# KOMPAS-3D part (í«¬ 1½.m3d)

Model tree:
1. Эскиз:1
2. Операция выдавливания:1
     Расстояние 1 = 2
3. Эскиз:2
4. Операция выдавливания:2
     Расстояние 1 = 5
5. Эскиз:3
6. Операция выдавливания:3
     Расстояние 1 = 2
7. Эскиз:4
8. Операция выдавливания:4
     Расстояние 1 = 60
9. Эскиз:5
10. Операция выдавливания:5
     Расстояние 1 = 2
11. Эскиз:6
12. Операция выдавливания:6
     Расстояние 1 = 4.5
13. Эскиз:7
14. Операция выдавливания:7
     Расстояние 1 = 2
15. Скругление:1
     Радиус = 1
16. Скругление:2
     Радиус = 1
17. Эскиз:8
18. Вырезать элемент выдавливания:1
     Расстояние 1 = 10; Угол 1 = 35
19. Эскиз:9
20. Вырезать элемент выдавливания:2
     Расстояние 1 = 10; Угол 1 = 35
21. Эскиз:10
22. Вырезать элемент выдавливания:3
     Расстояние 2 = 22; Расстояние 1 = 22; Угол 1 = 35
23. Эскиз:11
24. Вырезать элемент выдавливания:4
     Расстояние 2 = 2; Расстояние 1 = 2
25. Эскиз:12
26. Вырезать элемент выдавливания:5
     Расстояние 2 = 2; Расстояние 1 = 2; Угол 1 = 35
27. Эскиз:13
28. Вырезать элемент выдавливания:6
     Расстояние 2 = 2; Расстояние 1 = 122
29. Эскиз:15
30. Операция выдавливания:9
     Расстояние 1 = 10; Расстояние 2 = 0.5
